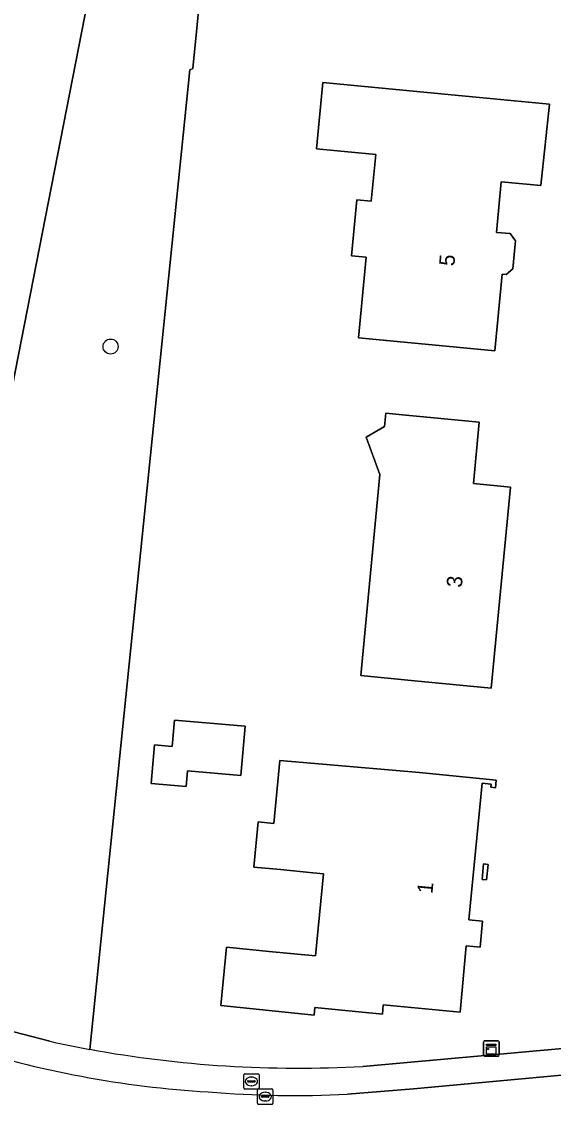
# Model space of a CAD drawing. Extents: x 162156 to 163172, y 378995 to 380779.
# Drawn here: x 162291.1 to 162325.6, y 380632.5 to 380702.7 of the extents above; entities that cross this region are included whole.
import ezdxf

# ---------------------------------------------------------------- set-up
doc = ezdxf.new("R2010")
doc.units = 0
for name, color, linetype in [('IMGEO_Boom', 7, 'Continuous'), ('IMGEO_Brandkraan', 7, 'Continuous'), ('IMGEO_Erf', 7, 'Continuous'), ('IMGEO_Groenvoorziening', 7, 'Continuous'), ('IMGEO_Kast', 7, 'Continuous'), ('IMGEO_Kolk', 7, 'Continuous'), ('IMGEO_Pand', 7, 'Continuous'), ('IMGEO_Pand_nummerreeks', 7, 'Continuous'), ('IMGEO_Rijbaan_lokaal_gesloten', 7, 'Continuous'), ('IMGEO_Voetpad_open', 7, 'Continuous')]:
    doc.layers.add(name, color=color, linetype=linetype)

msp = doc.modelspace()

# ---------------------------------------------------------------- linework, layer by layer
at = {"layer": 'IMGEO_Boom'}
msp.add_circle((162296.826, 380681.67), 0.489, dxfattribs=at)
at = {"layer": 'IMGEO_Brandkraan'}
for p, q in [((162305.46, 380633.589), (162305.46, 380634.441)), ((162305.535, 380634.515), (162306.387, 380634.515)), ((162305.948, 380634.295), (162305.973, 380634.295)), ((162306.461, 380634.441), (162306.461, 380633.589)), ((162305.719, 380634.009), (162305.719, 380634.021)), ((162306.157, 380633.972), (162305.759, 380633.972)), ((162305.762, 380634.058), (162306.16, 380634.058)), ((162305.971, 380633.735), (162305.946, 380633.735)), ((162306.203, 380634.021), (162306.203, 380634.009)), ((162306.387, 380633.515), (162305.535, 380633.515))]:
    msp.add_line(p, q, dxfattribs=at)
for points in [[(162305.46, 380633.589), (162305.46, 380634.441)], [(162305.535, 380634.515), (162306.387, 380634.515)], [(162306.461, 380634.441), (162306.461, 380633.589)], [(162306.387, 380633.515), (162305.535, 380633.515)]]:
    msp.add_lwpolyline(points, dxfattribs=at)
for centre, radius, start, end in [((162305.537, 380634.439), 0.0765, 91.55205, 178.44795), ((162305.537, 380634.439), 0.0765, 91.55205, 178.44795), ((162306.385, 380634.439), 0.0765, 1.55205, 88.44795), ((162306.385, 380634.439), 0.0765, 1.55205, 88.44795), ((162305.537, 380633.591), 0.0765, 181.55205, 268.44795), ((162305.537, 380633.591), 0.0765, 181.55205, 268.44795), ((162305.759, 380634.018), 0.0403, 85.87752, 175.75265), ((162305.756, 380634.008), 0.0366, 178.93798, 274.71019), ((162306.16, 380634.015), 0.043, 264.86636, 352.45326), ((162306.164, 380634.02), 0.0386, 1.73085, 96.63898), ((162306.385, 380633.591), 0.0765, 271.55205, 358.44795), ((162306.385, 380633.591), 0.0765, 271.55205, 358.44795)]:
    msp.add_arc(centre, radius, start, end, dxfattribs=at)
for centre, major_axis, ratio, start_param, end_param in [((162305.947, 380634.015), (-0.387, 0.002), 0.722429, 4.712389, 7.853982), ((162305.972, 380634.015), (-0.39, 0.002), 0.717154, 1.570796, 4.712389)]:
    msp.add_ellipse(centre, major_axis=major_axis, ratio=ratio, start_param=start_param, end_param=end_param, dxfattribs=at)
at = {"layer": 'IMGEO_Erf'}
for points in [[(162456.195, 380687.817), (162455.268, 380702.293), (162454.7, 380711.173), (162451.171, 380717.827), (162447.539, 380719.38), (162421.077, 380719.983), (162399.253, 380720.671), (162377.872, 380722.381), (162356.445, 380725.051), (162357.192, 380717.064), (162353.005, 380716.672), (162352.183, 380725.459), (162315.245, 380730.525), (162304.371, 380721.939), (162302.171, 380699.713), (162301.962, 380699.607), (162295.473, 380636.096)], [(162313.193, 380634.993), (162326.139, 380636.156), (162326.53, 380636.206), (162326.471, 380646.623), (162326.48, 380655.187)]]:
    msp.add_lwpolyline(points, dxfattribs=at)
for points in [[(162320.315, 380697.862), (162325.292, 380697.388), (162324.745, 380692.12), (162322.158, 380692.357), (162321.859, 380689.074), (162322.745, 380688.994), (162323.1, 380688.529), (162322.926, 380686.702), (162322.487, 380686.348), (162322.238, 380686.371), (162321.763, 380681.391), (162316.786, 380681.865), (162312.9, 380682.235), (162313.398, 380687.472), (162312.452, 380687.562), (162312.796, 380691.186), (162313.741, 380691.095), (162314.029, 380694.132), (162310.195, 380694.496), (162310.604, 380698.787)], [(162321.515, 380659.526), (162316.538, 380660), (162313.056, 380660.331), (162314.298, 380673.373), (162313.406, 380675.788), (162314.594, 380676.488), (162314.675, 380677.341), (162315.762, 380677.238), (162320.739, 380676.765), (162320.363, 380672.789), (162322.768, 380672.561)], [(162305.281, 380653.857), (162301.808, 380654.155), (162301.721, 380653.146), (162299.457, 380653.34), (162299.672, 380655.844), (162300.827, 380655.745), (162300.973, 380657.449), (162305.556, 380657.055)], [(162320.068, 380644.491), (162320.964, 380644.404), (162320.8, 380642.716), (162319.905, 380642.803), (162319.498, 380638.507), (162314.518, 380638.991), (162314.475, 380638.387), (162310.084, 380638.818), (162310.032, 380638.321), (162303.969, 380638.932), (162304.345, 380642.714), (162307.322, 380642.425), (162309.421, 380642.222), (162310.118, 380642.154), (162310.634, 380647.479), (162309.937, 380647.547), (162307.848, 380647.749), (162306.122, 380647.916), (162306.396, 380650.843), (162307.413, 380650.734), (162307.809, 380654.824), (162316.875, 380654.044), (162321.851, 380653.561), (162321.803, 380653.063), (162321.504, 380653.092), (162321.523, 380653.291), (162320.926, 380653.349)], [(162321.224, 380647.091), (162320.925, 380647.12), (162321.022, 380648.116), (162321.32, 380648.087)]]:
    msp.add_lwpolyline(points, close=True, dxfattribs=at)
msp.add_arc((162308.978, 380710.164), 75.289, 259.66682, 273.2095, dxfattribs=at)
at = {"layer": 'IMGEO_Groenvoorziening'}
for points in [[(162301.962, 380699.607), (162302.171, 380699.713), (162304.371, 380721.939), (162315.245, 380730.525), (162312.639, 380730.931), (162304.88, 380724.402), (162303.091, 380720.691), (162301.711, 380710.396), (162300.695, 380708.651), (162298.025, 380708.015), (162296.259, 380708.847), (162296.214, 380708.615), (162295.923, 380707.125), (162290.44, 380679.036), (162288.388, 380677.953), (162286.154, 380652.817)], [(162265.146, 380699.959), (162273.596, 380683.03), (162278.555, 380672.901), (162278.583, 380672.846), (162278.611, 380672.791), (162288.388, 380677.953), (162290.44, 380679.036), (162295.923, 380707.125), (162296.214, 380708.615)], [(162295.473, 380636.096), (162301.962, 380699.607)], [(162286.866, 380643.388), (162286.824, 380641.498), (162286.587, 380638.428), (162288.183, 380637.845), (162292.888, 380636.615)]]:
    msp.add_lwpolyline(points, dxfattribs=at)
msp.add_arc((162308.715, 380708.75), 73.851, 257.62463, 259.67027, dxfattribs=at)
at = {"layer": 'IMGEO_Kast'}
for p, q in [((162321.028, 380635.725), (162321.028, 380636.566)), ((162321.028, 380636.566), (162321.028, 380635.725)), ((162321.103, 380636.65), (162321.944, 380636.65)), ((162321.944, 380636.65), (162321.103, 380636.65)), ((162322.028, 380636.575), (162322.028, 380635.734)), ((162322.028, 380635.734), (162322.028, 380636.575)), ((162321.953, 380635.65), (162321.112, 380635.65)), ((162321.112, 380635.65), (162321.953, 380635.65))]:
    msp.add_line(p, q, dxfattribs=at)
for points in [[(162321.223, 380636.44), (162321.823, 380636.44), (162321.823, 380636.355), (162321.223, 380636.355), (162321.223, 380636.44)], [(162321.223, 380636.265), (162321.823, 380636.265), (162321.823, 380635.776), (162321.223, 380635.776), (162321.223, 380636.265)]]:
    msp.add_lwpolyline(points, dxfattribs=at)
msp.add_circle((162321.307, 380636.114), 0.0377, dxfattribs=at)
for centre, start, end in [((162321.106, 380636.572), 92.4484, 184.28452), ((162321.106, 380636.572), 92.4484, 184.28452), ((162321.95, 380636.572), 2.4484, 94.28452), ((162321.95, 380636.572), 2.4484, 94.28452), ((162321.106, 380635.728), 182.4484, 274.28452), ((162321.106, 380635.728), 182.4484, 274.28452), ((162321.95, 380635.728), 272.4484, 4.28452), ((162321.95, 380635.728), 272.4484, 4.28452)]:
    msp.add_arc(centre, 0.0779, start, end, dxfattribs=at)
at = {"layer": 'IMGEO_Kolk'}
for p, q in [((162306.357, 380632.603), (162306.357, 380633.455)), ((162306.432, 380633.529), (162307.284, 380633.529)), ((162306.616, 380633.023), (162306.616, 380633.035)), ((162307.054, 380632.986), (162306.656, 380632.986)), ((162306.659, 380633.072), (162307.057, 380633.072)), ((162306.845, 380633.309), (162306.87, 380633.309)), ((162307.1, 380633.035), (162307.1, 380633.023)), ((162307.358, 380633.455), (162307.358, 380632.603)), ((162307.284, 380632.529), (162306.432, 380632.529)), ((162306.868, 380632.749), (162306.843, 380632.749))]:
    msp.add_line(p, q, dxfattribs=at)
for points in [[(162306.357, 380632.603), (162306.357, 380633.455)], [(162306.432, 380633.529), (162307.284, 380633.529)], [(162307.358, 380633.455), (162307.358, 380632.603)], [(162307.284, 380632.529), (162306.432, 380632.529)]]:
    msp.add_lwpolyline(points, dxfattribs=at)
for centre, radius, start, end in [((162306.434, 380633.453), 0.0765, 91.55205, 178.44795), ((162306.434, 380633.453), 0.0765, 91.55205, 178.44795), ((162306.656, 380633.032), 0.0403, 85.87752, 175.75265), ((162306.653, 380633.022), 0.0366, 178.93798, 274.71019), ((162307.057, 380633.029), 0.043, 264.86636, 352.45326), ((162307.061, 380633.034), 0.0386, 1.73085, 96.63898), ((162307.282, 380633.453), 0.0765, 1.55205, 88.44795), ((162307.282, 380633.453), 0.0765, 1.55205, 88.44795), ((162306.434, 380632.605), 0.0765, 181.55205, 268.44795), ((162306.434, 380632.605), 0.0765, 181.55205, 268.44795), ((162307.282, 380632.605), 0.0765, 271.55205, 358.44795), ((162307.282, 380632.605), 0.0765, 271.55205, 358.44795)]:
    msp.add_arc(centre, radius, start, end, dxfattribs=at)
for centre, major_axis, ratio, start_param, end_param in [((162306.844, 380633.029), (-0.387, 0.002), 0.722429, 4.712389, 7.853982), ((162306.869, 380633.029), (-0.39, 0.002), 0.717154, 1.570796, 4.712389)]:
    msp.add_ellipse(centre, major_axis=major_axis, ratio=ratio, start_param=start_param, end_param=end_param, dxfattribs=at)
at = {"layer": 'IMGEO_Pand'}
for points in [[(162320.315, 380697.862), (162310.604, 380698.787), (162310.195, 380694.496), (162314.029, 380694.132), (162313.741, 380691.095), (162312.796, 380691.186), (162312.452, 380687.562), (162313.398, 380687.472), (162312.9, 380682.235), (162316.786, 380681.865), (162321.763, 380681.391), (162322.238, 380686.371), (162322.487, 380686.348), (162322.926, 380686.702), (162323.1, 380688.529), (162322.745, 380688.994), (162321.859, 380689.074), (162322.158, 380692.357), (162324.745, 380692.12), (162325.292, 380697.388)], [(162316.538, 380660), (162321.515, 380659.526), (162322.768, 380672.561), (162320.363, 380672.789), (162320.739, 380676.765), (162315.762, 380677.238), (162314.675, 380677.341), (162314.594, 380676.488), (162313.406, 380675.788), (162314.298, 380673.373), (162313.056, 380660.331)], [(162305.556, 380657.055), (162300.973, 380657.449), (162300.827, 380655.745), (162299.672, 380655.844), (162299.457, 380653.34), (162301.721, 380653.146), (162301.808, 380654.155), (162305.281, 380653.857)], [(162309.421, 380642.222), (162307.322, 380642.425), (162304.345, 380642.714), (162303.969, 380638.932), (162310.032, 380638.321), (162310.084, 380638.818), (162314.475, 380638.387), (162314.518, 380638.991), (162319.498, 380638.507), (162319.905, 380642.803), (162320.8, 380642.716), (162320.964, 380644.404), (162320.068, 380644.491), (162320.926, 380653.349), (162321.523, 380653.291), (162321.504, 380653.092), (162321.803, 380653.063), (162321.851, 380653.561), (162316.875, 380654.044), (162307.809, 380654.824), (162307.413, 380650.734), (162306.396, 380650.843), (162306.122, 380647.916), (162307.848, 380647.749), (162309.937, 380647.547), (162310.634, 380647.479), (162310.118, 380642.154)], [(162321.32, 380648.087), (162321.022, 380648.116), (162320.925, 380647.12), (162321.224, 380647.091)]]:
    msp.add_lwpolyline(points, close=True, dxfattribs=at)
at = {"layer": 'IMGEO_Rijbaan_lokaal_gesloten'}
msp.add_lwpolyline([(162462.779, 380646.893), (162434.772, 380644.509), (162430.746, 380644.14), (162421.757, 380643.305), (162411.727, 380642.392), (162337.675, 380635.531), (162334.069, 380635.183), (162326.307, 380634.434), (162316.483, 380633.533), (162312.194, 380633.191)], dxfattribs=at)
for centre, radius, start, end in [((162307.22, 380700.224), 67.013, 252.34085, 266.53125), ((162308.722, 380699.115), 66.015, 265.17086, 273.01441)]:
    msp.add_arc(centre, radius, start, end, dxfattribs=at)
at = {"layer": 'IMGEO_Voetpad_open'}
for points in [[(162292.888, 380636.615), (162288.183, 380637.845), (162286.587, 380638.428), (162284.739, 380639.104), (162278.855, 380641.254), (162268.543, 380644.781), (162259.036, 380647.044)], [(162312.194, 380633.191), (162316.483, 380633.533), (162326.307, 380634.434), (162326.268, 380634.832), (162326.139, 380636.156), (162313.193, 380634.993)]]:
    msp.add_lwpolyline(points, dxfattribs=at)
for centre, radius, start, end in [((162308.715, 380708.75), 73.851, 257.62463, 259.67027), ((162307.22, 380700.224), 67.013, 252.34085, 266.53125), ((162308.978, 380710.164), 75.289, 259.66682, 273.2095), ((162308.722, 380699.115), 66.015, 265.17086, 273.01441)]:
    msp.add_arc(centre, radius, start, end, dxfattribs=at)

# ---------------------------------------------------------------- texts
at = {"layer": 'IMGEO_Pand_nummerreeks'}
for s, rotation, p in [('5', 84.79613, (162319.126, 380686.858)), ('3', 84.50927, (162319.607, 380666.011)), ('1', 84.50262, (162317.703, 380646.158))]:
    msp.add_text(s, height=1, rotation=rotation, dxfattribs=at).set_placement(p)

doc.saveas('drawing.dxf')
